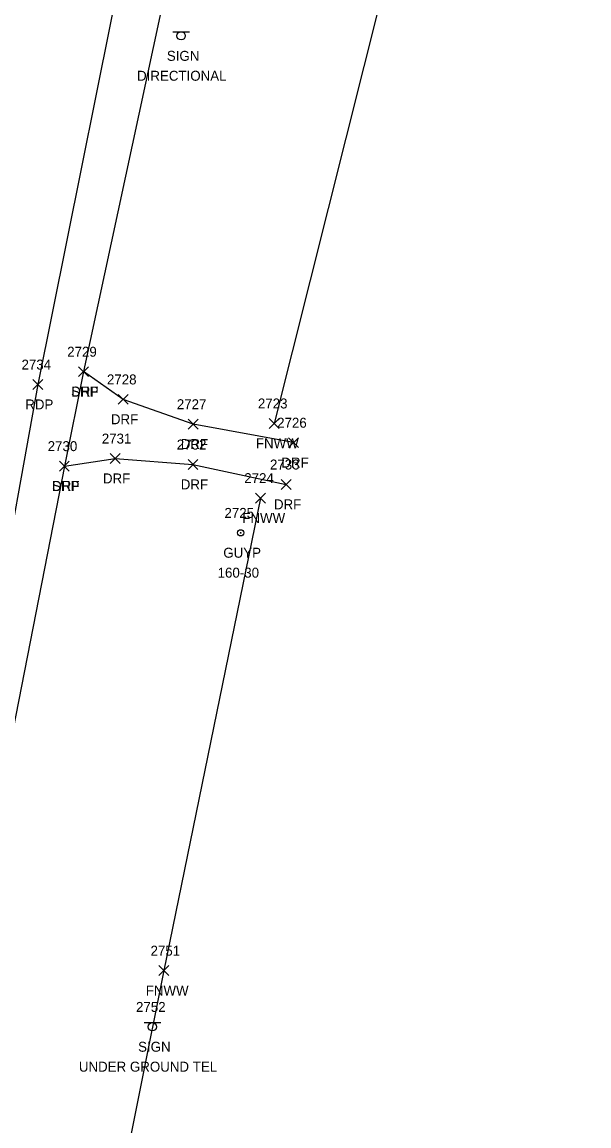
# Model space of a CAD drawing. Extents: x 1443071 to 1445292, y 614024 to 622563.
# Drawn here: x 1444119.8 to 1444233.7, y 620105.8 to 620327.5 of the extents above; entities that cross this region are included whole.
import ezdxf

# ---------------------------------------------------------------- set-up
doc = ezdxf.new("R2010")
doc.units = 0
for name, color, linetype in [('L_A', 7, 'Continuous'), ('L_I', 7, 'Continuous'), ('L_TIC', 7, 'Continuous'), ('LFNC', 7, 'Continuous'), ('P_A', 7, 'Continuous'), ('P_I', 7, 'Continuous'), ('P_TIC', 7, 'Continuous'), ('PET', 7, 'Continuous'), ('PSP', 7, 'Continuous'), ('R_A', 7, 'Continuous'), ('R_I', 7, 'Continuous'), ('R_TIC', 7, 'Continuous'), ('RDF', 7, 'Continuous'), ('S_A', 7, 'Continuous'), ('S_C', 7, 'Continuous'), ('S_I', 7, 'Continuous'), ('SSGN', 7, 'Continuous'), ('U_A', 7, 'Continuous'), ('U_C', 7, 'Continuous'), ('U_I', 7, 'Continuous'), ('UPGW', 7, 'Continuous')]:
    doc.layers.add(name, color=color, linetype=linetype)

msp = doc.modelspace()

# ---------------------------------------------------------------- linework, layer by layer
at = {"layer": 'L_TIC'}
for points in [[(1444169.47, 620245.87), (1444171.47, 620247.87)], [(1444171.47, 620245.87), (1444169.47, 620247.87)], [(1444166.73, 620230.87), (1444168.73, 620232.87)], [(1444168.73, 620230.87), (1444166.73, 620232.87)], [(1444147.34, 620135.96), (1444149.34, 620137.96)], [(1444149.34, 620135.96), (1444147.34, 620137.96)]]:
    msp.add_lwpolyline(points, dxfattribs=at)
at = {"layer": 'LFNC'}
for points in [[(1444419.19, 620873.15), (1444374.8, 620882.12), (1444324.82, 620892.87), (1444313.12, 620833.07), (1444292.13, 620722.15), (1444270.22, 620633.1), (1444246.55, 620538.96), (1444227.66, 620469.15), (1444211.24, 620407.8), (1444195.72, 620347.39), (1444170.47, 620246.87)], [(1444167.73, 620231.87), (1444148.34, 620136.96), (1444138.8, 620089.58), (1444124.8, 620023.28), (1444117.45, 619982.25)]]:
    msp.add_lwpolyline(points, dxfattribs=at)
at = {"layer": 'P_TIC'}
for points in [[(1444131.16, 620256.26), (1444133.16, 620258.26)], [(1444133.16, 620256.26), (1444131.16, 620258.26)], [(1444121.97, 620253.68), (1444123.97, 620255.68)], [(1444123.97, 620253.68), (1444121.97, 620255.68)], [(1444127.32, 620237.3), (1444129.32, 620239.3)], [(1444129.32, 620237.3), (1444127.32, 620239.3)]]:
    msp.add_lwpolyline(points, dxfattribs=at)
at = {"layer": 'PET'}
msp.add_lwpolyline([(1444393.99, 621275.61), (1444360.23, 621155.32), (1444345.74, 621103.98), (1444299.41, 620941.8), (1444273.27, 620844.52), (1444244.09, 620730.97), (1444221.37, 620651.37), (1444196.75, 620548.06), (1444177.44, 620486.23), (1444161.6, 620423.84), (1444143.45, 620356.38), (1444122.97, 620254.68), (1444105.94, 620160.17), (1444094.56, 620089.52), (1444083.91, 620011.71), (1444077.6, 619958.52), (1444073.05, 619913.75)], dxfattribs=at)
at = {"layer": 'PSP'}
msp.add_lwpolyline([(1444228.91, 620648.98), (1444202.76, 620547.52), (1444186.16, 620483.96), (1444170.45, 620422.38), (1444153.07, 620354.47), (1444132.16, 620257.26), (1444128.32, 620238.3), (1444112.75, 620158.8), (1444100.76, 620089.32), (1444087.94, 620010.71), (1444079.9, 619958.71), (1444074.06, 619920.41), (1444074.5, 619920), (1444074.51, 619919.99), (1444073.05, 619913.75)], dxfattribs=at)
at = {"layer": 'R_TIC'}
for points in [[(1444131.16, 620256.26), (1444133.16, 620258.26)], [(1444133.16, 620256.26), (1444131.16, 620258.26)], [(1444139.14, 620250.7), (1444141.14, 620252.7)], [(1444141.14, 620250.7), (1444139.14, 620252.7)], [(1444153.18, 620245.72), (1444155.18, 620247.72)], [(1444155.18, 620245.72), (1444153.18, 620247.72)], [(1444173.39, 620242), (1444175.39, 620244)], [(1444175.39, 620242), (1444173.39, 620244)], [(1444137.54, 620238.82), (1444139.54, 620240.82)], [(1444139.54, 620238.82), (1444137.54, 620240.82)], [(1444153.17, 620237.62), (1444155.17, 620239.62)], [(1444155.17, 620237.62), (1444153.17, 620239.62)], [(1444127.32, 620237.3), (1444129.32, 620239.3)], [(1444129.32, 620237.3), (1444127.32, 620239.3)], [(1444171.9, 620233.61), (1444173.9, 620235.61)], [(1444173.9, 620233.61), (1444171.9, 620235.61)]]:
    msp.add_lwpolyline(points, dxfattribs=at)
at = {"layer": 'RDF'}
for points in [[(1444174.39, 620243), (1444154.18, 620246.72), (1444140.14, 620251.7), (1444132.16, 620257.26)], [(1444128.32, 620238.3), (1444138.54, 620239.82), (1444154.17, 620238.62), (1444172.9, 620234.61)]]:
    msp.add_lwpolyline(points, dxfattribs=at)
at = {"layer": 'SSGN'}
for p, q in [((1444150.14, 620325.54), (1444153.47, 620325.54)), ((1444151.79, 620324.71), (1444151.79, 620324.71)), ((1444144.35, 620126.52), (1444147.69, 620126.52)), ((1444146, 620125.69), (1444146, 620125.69))]:
    msp.add_line(p, q, dxfattribs=at)
for centre in [(1444151.79, 620324.71), (1444146, 620125.69)]:
    msp.add_circle(centre, 0.833, dxfattribs=at)
at = {"layer": 'UPGW'}
for radius in [0.625, 0.0833]:
    msp.add_circle((1444163.75, 620224.89), radius, dxfattribs=at)

# ---------------------------------------------------------------- texts
at = {"layer": 'L_A'}
for p in [(1444166.81, 620241.87), (1444164.08, 620226.87), (1444144.68, 620131.96)]:
    msp.add_text('FNWW', height=2, dxfattribs=at).set_placement(p)
at = {"layer": 'L_I'}
for s, p in [('2723', (1444167.21, 620249.87)), ('2724', (1444164.47, 620234.87)), ('2751', (1444145.64, 620139.96))]:
    msp.add_text(s, height=2, dxfattribs=at).set_placement(p)
at = {"layer": 'P_A'}
for s, p in [('SHP', (1444129.69, 620252.26)), ('RDP', (1444120.46, 620249.68)), ('SHP', (1444125.85, 620233.3))]:
    msp.add_text(s, height=2, dxfattribs=at).set_placement(p)
at = {"layer": 'P_I'}
for s, p in [('2729', (1444128.89, 620260.26)), ('2734', (1444119.71, 620257.68)), ('2730', (1444124.97, 620241.3))]:
    msp.add_text(s, height=2, dxfattribs=at).set_placement(p)
at = {"layer": 'R_A'}
for p in [(1444129.69, 620252.26), (1444137.67, 620246.7), (1444151.72, 620241.72), (1444171.93, 620238), (1444125.85, 620233.3), (1444136.07, 620234.82), (1444151.71, 620233.62), (1444170.44, 620229.61)]:
    msp.add_text('DRF', height=2, dxfattribs=at).set_placement(p)
at = {"layer": 'R_I'}
for s, p in [('2729', (1444128.89, 620260.26)), ('2728', (1444136.88, 620254.7)), ('2727', (1444150.92, 620249.72)), ('2726', (1444171.08, 620246)), ('2731', (1444135.84, 620242.82)), ('2730', (1444124.97, 620241.3)), ('2732', (1444150.91, 620241.62)), ('2733', (1444169.64, 620237.61))]:
    msp.add_text(s, height=2, dxfattribs=at).set_placement(p)
at = {"layer": 'S_A'}
for p in [(1444148.92, 620319.69), (1444143.14, 620120.67)]:
    msp.add_text('SIGN', height=2, dxfattribs=at).set_placement(p)
at = {"layer": 'S_C'}
for s, p in [('DIRECTIONAL', (1444142.93, 620315.69)), ('UNDER GROUND TEL', (1444131.24, 620116.67))]:
    msp.add_text(s, height=2, dxfattribs=at).set_placement(p)
at = {"layer": 'S_I'}
msp.add_text('2752', height=2, dxfattribs=at).set_placement((1444142.72, 620128.67))
at = {"layer": 'U_A'}
msp.add_text('GUYP', height=2, dxfattribs=at).set_placement((1444160.26, 620219.89))
at = {"layer": 'U_C'}
msp.add_text('160-30', height=2, dxfattribs=at).set_placement((1444159.12, 620215.89))
at = {"layer": 'U_I'}
msp.add_text('2725', height=2, dxfattribs=at).set_placement((1444160.49, 620227.89))

doc.saveas('drawing.dxf')
